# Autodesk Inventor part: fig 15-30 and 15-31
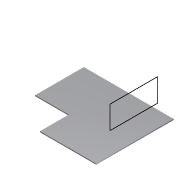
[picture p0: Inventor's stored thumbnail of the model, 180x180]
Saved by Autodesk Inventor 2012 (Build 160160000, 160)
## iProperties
Created: 2005-03
Part Number: fig 15-30 and 15-31
Document SubType Name: Sheet Metal
Designer: CADCIM
Manufacturer: Standard
Standards Organization: Custom
Density: 1 g/cm^3
Sheet Metal Rule: Default
Material: Default
Author: CADCIM
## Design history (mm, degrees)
node "Face1"
  sketch "Sketch1" dims "JacobiRadiusSize" = 0.5 (= Thickness)
    geometry: L1 (29.25, 32.25)-(-19.875, 32.25); L2 (-19.875, 32.25)-(-19.875, 5.625); L3 (-19.875, 5.625)-(-1.5, 5.625); L4 (-1.5, 5.625)-(-1.5, -10.125); L5 (-1.5, -10.125)-(29.25, -10.125); L6 (29.25, -10.125)-(29.25, 32.25)
    constraints: 12 end point, 4 parallel, 1 horizontal, 1 perpendicular
sketch "Sketch2"
  geometry: L1 (-12.475, 7.526)-(-25.013, 7.526); L2 (-25.013, 7.526)-(-25.013, 33.56); L3 (-25.013, 33.56)-(-12.475, 33.56); L4 (-12.475, 33.56)-(-12.475, 7.526)
  constraints: 8 end point, 2 parallel, 1 horizontal, 1 perpendicular
body "Solid1"
face "Plate1" dims "Thickness" = 0.5
other parameters: "BendRadius" = 0.5 (= Thickness), "BendReliefWidth" = 0.5 (= Thickness), "BendReliefDepth" = 0.25 (= 0.5 x Thickness), "CornerReliefSize" = 2 (= 4 x Thickness), "SeamGap" = 0.01, "MinimumRemnant" = 1 (= 2 x Thickness), "TransitionRadius" = 0.5 (= BendRadius), "d0" = 0.5 (= BendRadius), "GapSize" = 0.5 (= Thickness)
